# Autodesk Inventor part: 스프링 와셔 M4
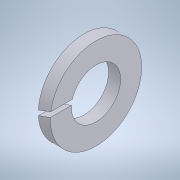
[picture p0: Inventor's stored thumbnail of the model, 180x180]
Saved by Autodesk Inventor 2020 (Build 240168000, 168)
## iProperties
Created: 2024-04
Part Number: 스프링 와셔 M4
Material: 강철, 연강
Description: 스프링 와셔
Document SubType Name: Modeling
Designer: oem
Density: 7.85 g/cm^3
Appearance: 기본값
Author: jhkim
Sending System: Autodesk Inventor 2025
Preprocessor: ST-DEVELOPER v20
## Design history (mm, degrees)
feature "Solid1"
node "솔리드1"
